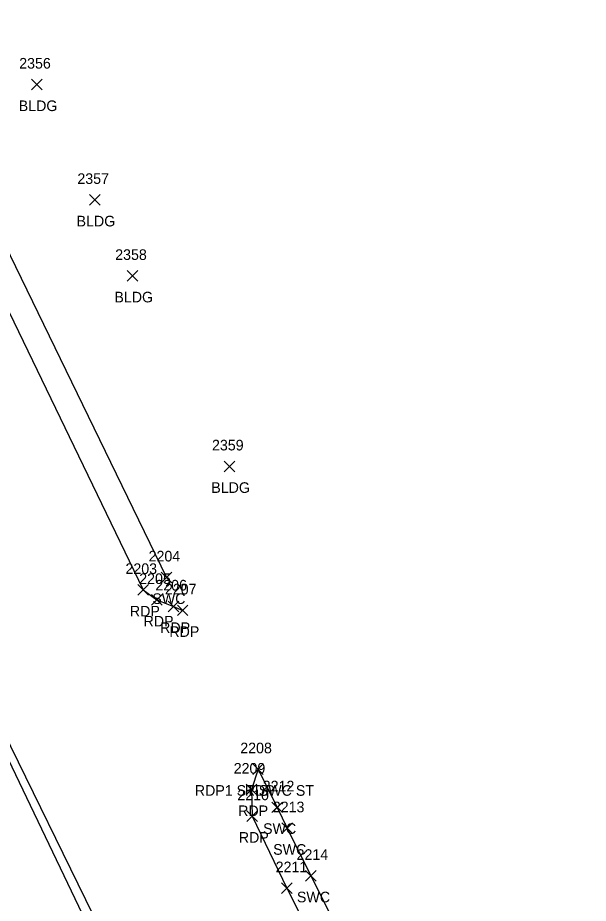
# Model space of a CAD drawing. Extents: x 1635588 to 1637550, y 621583 to 623638.
# Drawn here: x 1636479.5 to 1636586.9, y 623053.3 to 623220.1 of the extents above; entities that cross this region are included whole.
import ezdxf

# ---------------------------------------------------------------- set-up
doc = ezdxf.new("R2010")
doc.units = 0
for name, color, linetype in [('L_A', 7, 'Continuous'), ('L_I', 7, 'Continuous'), ('L_TIC', 7, 'Continuous'), ('P_A', 7, 'Continuous'), ('P_I', 7, 'Continuous'), ('P_TIC', 7, 'Continuous'), ('PET', 7, 'Continuous'), ('PSP', 7, 'Continuous'), ('R_A', 7, 'Continuous'), ('R_I', 7, 'Continuous'), ('R_TIC', 7, 'Continuous'), ('RSW', 7, 'Continuous')]:
    doc.layers.add(name, color=color, linetype=linetype)

msp = doc.modelspace()

# ---------------------------------------------------------------- linework, layer by layer
at = {"layer": 'L_TIC'}
for points in [[(1636482.13, 623206.48), (1636484.13, 623208.48)], [(1636484.13, 623206.48), (1636482.13, 623208.48)], [(1636493.02, 623184.76), (1636495.02, 623186.76)], [(1636495.02, 623184.76), (1636493.02, 623186.76)], [(1636500.14, 623170.45), (1636502.14, 623172.45)], [(1636502.14, 623170.45), (1636500.14, 623172.45)], [(1636518.37, 623134.57), (1636520.37, 623136.57)], [(1636520.37, 623134.57), (1636518.37, 623136.57)]]:
    msp.add_lwpolyline(points, dxfattribs=at)
at = {"layer": 'P_TIC'}
for points in [[(1636502.15, 623111.3), (1636504.15, 623113.3)], [(1636504.15, 623111.3), (1636502.15, 623113.3)], [(1636504.74, 623109.41), (1636506.74, 623111.41)], [(1636506.74, 623109.41), (1636504.74, 623111.41)], [(1636507.84, 623108.19), (1636509.84, 623110.19)], [(1636509.84, 623108.19), (1636507.84, 623110.19)], [(1636509.58, 623107.45), (1636511.58, 623109.45)], [(1636511.58, 623107.45), (1636509.58, 623109.45)], [(1636523.76, 623077.53), (1636525.76, 623079.53)], [(1636525.76, 623077.53), (1636523.76, 623079.53)], [(1636522.53, 623073.7), (1636524.53, 623075.7)], [(1636524.53, 623073.7), (1636522.53, 623075.7)], [(1636522.65, 623068.69), (1636524.65, 623070.69)], [(1636524.65, 623068.69), (1636522.65, 623070.69)], [(1636529.21, 623055.13), (1636531.21, 623057.13)], [(1636531.21, 623055.13), (1636529.21, 623057.13)]]:
    msp.add_lwpolyline(points, dxfattribs=at)
at = {"layer": 'PET'}
for points in [[(1636457.94, 623205.96), (1636503.15, 623112.3), (1636505.74, 623110.41), (1636508.84, 623109.19), (1636510.58, 623108.45)], [(1636496.54, 623045.3), (1636474, 623091.38)], [(1636524.76, 623078.53), (1636523.53, 623074.7), (1636523.65, 623069.69), (1636530.21, 623056.13), (1636548.33, 623020.32), (1636566.47, 622984.44), (1636591.76, 622939.94), (1636601.42, 622922.26), (1636608.34, 622909.96), (1636613.87, 622901.12), (1636616.68, 622897.25), (1636624.11, 622894.09), (1636627.52, 622895.36), (1636632.87, 622898.34)]]:
    msp.add_lwpolyline(points, dxfattribs=at)
at = {"layer": 'PSP'}
msp.add_lwpolyline([(1636412.61, 623220.07), (1636436.6, 623167.3), (1636456.23, 623125.07), (1636460.67, 623115.98), (1636475.52, 623084.87), (1636494.51, 623045.42), (1636524.16, 622986.51), (1636530.74, 622972.24), (1636554.07, 622925.3), (1636577.18, 622886.3), (1636601.72, 622847.41), (1636613.46, 622830.09), (1636645.38, 622782.47), (1636700.61, 622698.86), (1636734.28, 622648.07), (1636752.12, 622619.3), (1636752.46, 622616.81), (1636755.34, 622613.42), (1636810.04, 622534.39), (1636855.63, 622465.66), (1636874.76, 622437.49), (1636904.15, 622393.55)], dxfattribs=at)
at = {"layer": 'R_TIC'}
for points in [[(1636506.51, 623113.66), (1636508.51, 623115.66)], [(1636508.51, 623113.66), (1636506.51, 623115.66)], [(1636523.76, 623077.53), (1636525.76, 623079.53)], [(1636525.76, 623077.53), (1636523.76, 623079.53)], [(1636527.35, 623070.35), (1636529.35, 623072.35)], [(1636529.35, 623070.35), (1636527.35, 623072.35)], [(1636529.25, 623066.42), (1636531.25, 623068.42)], [(1636531.25, 623066.42), (1636529.25, 623068.42)], [(1636533.71, 623057.46), (1636535.71, 623059.46)], [(1636535.71, 623057.46), (1636533.71, 623059.46)]]:
    msp.add_lwpolyline(points, dxfattribs=at)
at = {"layer": 'RSW'}
for points in [[(1636462.26, 623207.84), (1636507.51, 623114.66)], [(1636524.76, 623078.53), (1636528.35, 623071.35), (1636530.25, 623067.42), (1636534.71, 623058.46), (1636552.77, 623022.45), (1636571.37, 622985.37), (1636595.71, 622942.66), (1636605.64, 622925.15), (1636612.41, 622912.41), (1636617.8, 622903.4), (1636619.7, 622901.31), (1636620.99, 622899.9), (1636623.17, 622899.6), (1636625.06, 622899.88), (1636629.3, 622902.63)]]:
    msp.add_lwpolyline(points, dxfattribs=at)

# ---------------------------------------------------------------- texts
at = {"layer": 'L_A'}
for p in [(1636479.72, 623202.48), (1636490.61, 623180.76), (1636497.73, 623166.45), (1636515.96, 623130.57)]:
    msp.add_text('BLDG', height=2, dxfattribs=at).set_placement(p)
at = {"layer": 'L_I'}
for s, p in [('2356', (1636479.81, 623210.48)), ('2357', (1636490.76, 623188.76)), ('2358', (1636497.88, 623174.45)), ('2359', (1636516.1, 623138.57))]:
    msp.add_text(s, height=2, dxfattribs=at).set_placement(p)
at = {"layer": 'P_A'}
for p in [(1636500.64, 623107.3), (1636503.22, 623105.41), (1636506.33, 623104.19), (1636508.07, 623103.45), (1636522.25, 623073.53), (1636521.02, 623069.7), (1636521.14, 623064.69)]:
    msp.add_text('RDP', height=2, dxfattribs=at).set_placement(p)
at = {"layer": 'P_I'}
for s, p in [('2203', (1636499.81, 623115.3)), ('2205', (1636502.4, 623113.41)), ('2206', (1636505.44, 623112.19)), ('2207', (1636507.24, 623111.45)), ('2208', (1636521.42, 623081.53)), ('2209', (1636520.18, 623077.7)), ('2210', (1636520.87, 623072.69)), ('2211', (1636528.08, 623059.13))]:
    msp.add_text(s, height=2, dxfattribs=at).set_placement(p)
at = {"layer": 'R_A'}
for s, p in [('SWC', (1636504.87, 623109.66)), ('RDP1 ST SWC ST', (1636512.86, 623073.53)), ('SWC', (1636525.71, 623066.35)), ('SWC', (1636527.61, 623062.42)), ('SWC', (1636532.08, 623053.46))]:
    msp.add_text(s, height=2, dxfattribs=at).set_placement(p)
at = {"layer": 'R_I'}
for s, p in [('2204', (1636504.17, 623117.66)), ('2208', (1636521.42, 623081.53)), ('2212', (1636525.65, 623074.35)), ('2213', (1636527.55, 623070.42)), ('2214', (1636532.02, 623061.46))]:
    msp.add_text(s, height=2, dxfattribs=at).set_placement(p)

doc.saveas('drawing.dxf')
